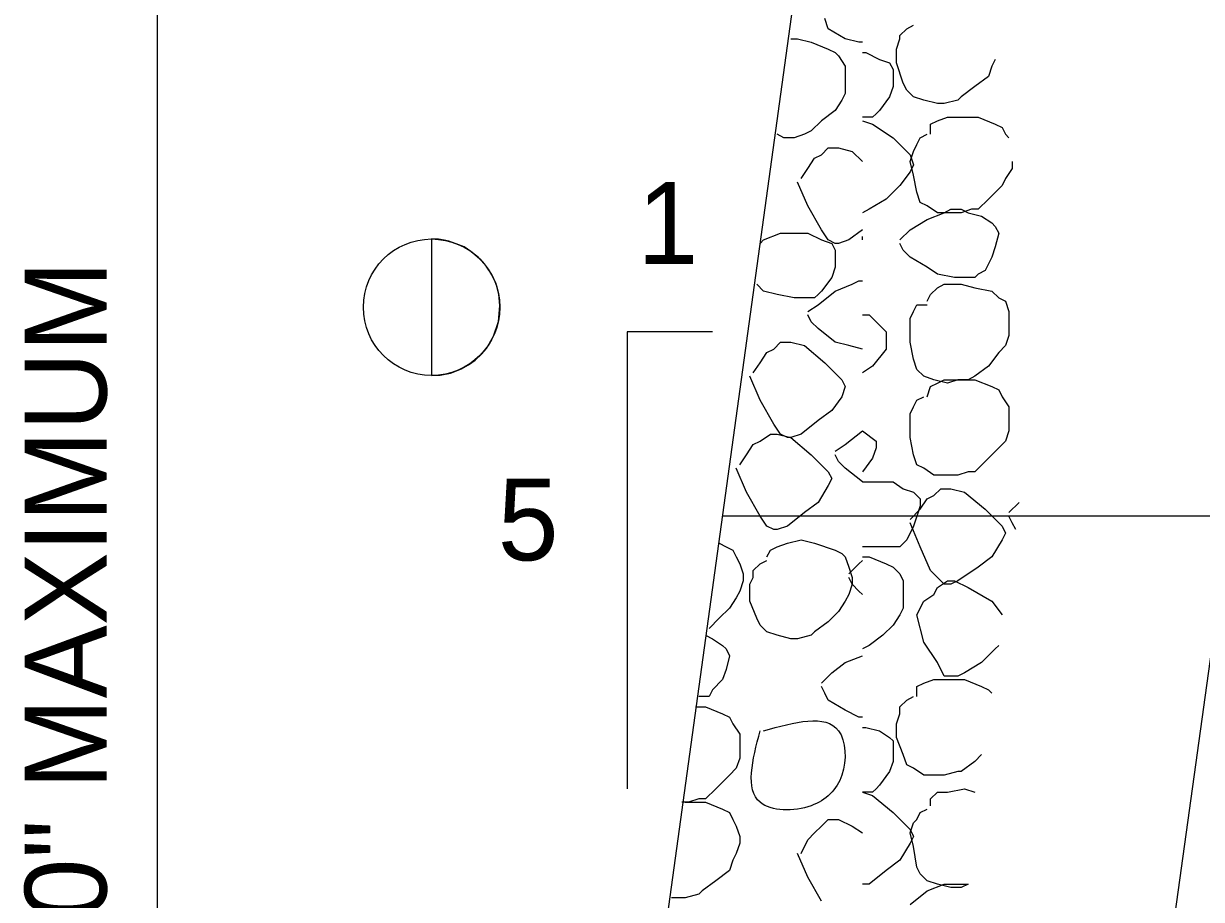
# Model space of a CAD drawing. Extents: x 593 to 1473, y 721 to 1315.
# Drawn here: x 885.01 to 928.22, y 1167.96 to 1200.08 of the extents above; entities that cross this region are included whole.
import ezdxf

# ---------------------------------------------------------------- set-up
doc = ezdxf.new("R2010")
doc.units = 0
doc.layers.add('1', color=7, linetype='Continuous')
doc.layers.add('2', color=7, linetype='Continuous')

msp = doc.modelspace()

# ---------------------------------------------------------------- linework, layer by layer
at = {"layer": '1'}
msp.add_lwpolyline([(899.982, 1192.182), (899.982, 1187.178), (900.301, 1187.189), (900.675, 1187.263), (901.08, 1187.423), (901.335, 1187.562), (901.581, 1187.743), (901.815, 1187.957), (901.996, 1188.17), (902.252, 1188.618), (902.433, 1189.152), (902.487, 1189.739), (902.444, 1190.155), (902.348, 1190.539), (902.188, 1190.88), (901.986, 1191.19), (901.698, 1191.499), (901.421, 1191.723), (901.175, 1191.894), (900.877, 1192.001), (900.611, 1192.108), (900.44, 1192.14), (900.238, 1192.172)], close=True, dxfattribs=at)
msp.add_circle((899.982, 1189.68), 2.502, dxfattribs=at)
at = {"layer": '2'}
for p, q in [((889.933, 1144.896), (889.933, 1219.146)), ((905.533, 1144.896), (915.783, 1219.146)), ((924.158, 1145.021), (934.408, 1219.146)), ((899.982, 1192.182), (899.982, 1187.178)), ((907.158, 1188.771), (907.158, 1172.021)), ((910.283, 1188.771), (907.158, 1188.771)), ((962.283, 1182.021), (910.658, 1182.021))]:
    msp.add_line(p, q, dxfattribs=at)
for points in [[(914.533, 1199.896), (914.408, 1200.271)], [(915.158, 1199.521), (914.533, 1199.896)], [(917.158, 1199.646), (917.408, 1199.896)], [(917.408, 1199.896), (917.658, 1200.021)], [(913.158, 1199.521), (913.408, 1199.521)], [(913.408, 1199.521), (913.908, 1199.396)], [(915.658, 1199.396), (915.158, 1199.521)], [(917.033, 1199.146), (917.158, 1199.521)], [(917.158, 1199.521), (917.158, 1199.646)], [(913.908, 1199.396), (914.533, 1199.146)], [(914.533, 1199.146), (914.783, 1199.021)], [(914.783, 1199.021), (914.908, 1198.896)], [(915.783, 1199.396), (915.658, 1199.396)], [(915.783, 1199.021), (915.908, 1199.021)], [(915.908, 1199.021), (916.408, 1198.771)], [(917.033, 1198.646), (917.033, 1199.146)], [(914.908, 1198.896), (915.158, 1198.521)], [(916.408, 1198.771), (916.783, 1198.646)], [(916.783, 1198.646), (916.908, 1198.396)], [(917.283, 1197.896), (917.033, 1198.646)], [(920.658, 1198.771), (920.533, 1198.521)], [(915.158, 1198.521), (915.158, 1198.146)], [(915.158, 1198.146), (915.158, 1197.896)], [(916.908, 1198.396), (916.908, 1198.271)], [(916.908, 1198.271), (916.908, 1197.771)], [(920.408, 1198.146), (919.908, 1197.771)], [(920.533, 1198.521), (920.408, 1198.146)], [(915.158, 1197.896), (915.158, 1197.521)], [(916.908, 1197.771), (916.783, 1197.396)], [(917.408, 1197.646), (917.283, 1197.896)], [(919.908, 1197.771), (919.408, 1197.396)], [(915.033, 1197.271), (914.783, 1196.896)], [(915.158, 1197.521), (915.033, 1197.271)], [(916.783, 1197.396), (916.408, 1196.896)], [(917.658, 1197.396), (917.408, 1197.646)], [(918.033, 1197.271), (917.658, 1197.396)], [(918.533, 1197.146), (918.033, 1197.271)], [(919.283, 1197.271), (918.783, 1197.146)], [(919.408, 1197.396), (919.283, 1197.271)], [(914.783, 1196.896), (914.283, 1196.521)], [(916.408, 1196.896), (916.283, 1196.771)], [(918.783, 1197.146), (918.533, 1197.146)], [(914.283, 1196.521), (913.908, 1196.146)], [(916.158, 1196.646), (915.783, 1196.646)], [(915.783, 1196.521), (916.158, 1196.396)], [(916.283, 1196.771), (916.158, 1196.646)], [(918.283, 1196.396), (918.533, 1196.521)], [(918.533, 1196.521), (918.908, 1196.646)], [(918.908, 1196.646), (919.533, 1196.646)], [(919.533, 1196.646), (920.033, 1196.646)], [(920.033, 1196.646), (920.658, 1196.396)], [(912.908, 1195.896), (912.658, 1196.021)], [(913.658, 1196.021), (913.283, 1195.896)], [(913.908, 1196.146), (913.658, 1196.021)], [(916.158, 1196.396), (916.908, 1195.896)], [(917.908, 1195.896), (918.158, 1196.021)], [(918.283, 1196.021), (918.283, 1196.396)], [(920.658, 1196.396), (920.908, 1196.271)], [(920.908, 1196.271), (921.033, 1196.021)], [(921.033, 1196.021), (921.158, 1195.896)], [(913.283, 1195.896), (912.908, 1195.896)], [(916.908, 1195.896), (917.533, 1195.271)], [(917.658, 1195.396), (917.783, 1195.646)], [(917.783, 1195.646), (917.908, 1195.896)], [(913.783, 1194.771), (914.033, 1195.146)], [(914.033, 1195.146), (914.283, 1195.271)], [(914.283, 1195.271), (914.533, 1195.521)], [(914.533, 1195.521), (914.783, 1195.521)], [(914.783, 1195.521), (914.908, 1195.521)], [(914.908, 1195.521), (915.408, 1195.396)], [(915.408, 1195.396), (915.783, 1195.021)], [(917.533, 1195.021), (917.658, 1195.396)], [(917.533, 1195.271), (917.658, 1194.896)], [(913.533, 1194.396), (913.783, 1194.771)], [(917.658, 1194.521), (917.533, 1195.021)], [(917.658, 1194.896), (917.533, 1194.646)], [(921.283, 1194.771), (921.033, 1194.396)], [(921.283, 1195.021), (921.283, 1194.771)], [(913.783, 1193.396), (913.408, 1194.271)], [(917.533, 1194.646), (917.158, 1194.146)], [(917.783, 1193.896), (917.658, 1194.521)], [(921.033, 1194.396), (920.908, 1194.146)], [(917.158, 1194.146), (916.658, 1193.646)], [(917.908, 1193.521), (917.783, 1193.896)], [(920.908, 1194.146), (920.408, 1193.646)], [(914.283, 1192.521), (913.783, 1193.396)], [(916.658, 1193.646), (916.033, 1193.271)], [(918.158, 1193.396), (917.908, 1193.521)], [(918.533, 1193.146), (918.158, 1193.396)], [(920.408, 1193.646), (920.033, 1193.271)], [(916.033, 1193.271), (915.783, 1193.146)], [(918.158, 1192.896), (918.783, 1193.146)], [(919.033, 1193.146), (918.533, 1193.146)], [(918.783, 1193.146), (919.033, 1193.271)], [(919.033, 1193.271), (919.408, 1193.271)], [(919.408, 1193.146), (919.033, 1193.146)], [(919.783, 1193.271), (919.408, 1193.146)], [(919.408, 1193.271), (919.658, 1193.146)], [(919.658, 1193.146), (920.158, 1193.021)], [(920.033, 1193.271), (919.783, 1193.271)], [(920.158, 1193.021), (920.533, 1192.771)], [(914.533, 1192.146), (914.283, 1192.521)], [(915.783, 1192.521), (915.283, 1192.146)], [(915.783, 1192.521), (915.783, 1192.521)], [(917.158, 1192.146), (917.533, 1192.521)], [(917.533, 1192.521), (918.158, 1192.896)], [(920.533, 1192.771), (920.658, 1192.646)], [(920.658, 1192.646), (920.783, 1192.396)], [(912.033, 1192.021), (912.158, 1192.146)], [(912.158, 1192.146), (912.783, 1192.396)], [(912.783, 1192.396), (913.033, 1192.396)], [(913.033, 1192.396), (913.408, 1192.396)], [(913.408, 1192.396), (913.783, 1192.396)], [(913.783, 1192.396), (914.283, 1192.146)], [(914.283, 1192.146), (914.658, 1192.021)], [(914.783, 1192.021), (914.533, 1192.146)], [(915.283, 1192.146), (914.908, 1192.021)], [(915.783, 1192.146), (915.783, 1192.271)], [(920.783, 1192.396), (920.658, 1191.896)], [(914.658, 1192.021), (914.783, 1191.771)], [(914.908, 1192.021), (914.783, 1192.021)], [(914.783, 1191.771), (914.783, 1191.646)], [(917.283, 1191.771), (917.158, 1192.021)], [(917.533, 1191.521), (917.283, 1191.771)], [(920.658, 1191.896), (920.533, 1191.521)], [(914.783, 1191.646), (914.783, 1191.146)], [(918.158, 1191.146), (917.533, 1191.521)], [(920.533, 1191.521), (920.283, 1191.021)], [(914.783, 1191.146), (914.658, 1190.771)], [(918.533, 1190.896), (918.158, 1191.146)], [(919.158, 1190.771), (918.533, 1190.896)], [(920.033, 1190.896), (919.908, 1190.771)], [(920.283, 1191.021), (920.033, 1190.896)], [(912.158, 1190.271), (911.908, 1190.521)], [(914.658, 1190.771), (914.283, 1190.271)], [(914.783, 1190.271), (915.408, 1190.521)], [(915.408, 1190.521), (915.658, 1190.646)], [(915.658, 1190.646), (915.783, 1190.646)], [(918.283, 1190.146), (918.533, 1190.396)], [(918.533, 1190.396), (918.783, 1190.521)], [(918.783, 1190.521), (919.408, 1190.521)], [(919.908, 1190.771), (919.158, 1190.771)], [(919.408, 1190.521), (919.908, 1190.396)], [(919.908, 1190.396), (920.533, 1190.271)], [(912.658, 1190.146), (912.158, 1190.271)], [(913.283, 1190.021), (912.658, 1190.146)], [(914.033, 1190.021), (913.283, 1190.021)], [(914.158, 1190.146), (914.033, 1190.021)], [(914.158, 1189.771), (914.783, 1190.271)], [(914.283, 1190.271), (914.158, 1190.146)], [(918.158, 1189.896), (918.283, 1190.146)], [(920.533, 1190.271), (920.783, 1190.021)], [(920.783, 1190.021), (921.033, 1189.896)], [(913.783, 1189.521), (914.158, 1189.771)], [(917.533, 1189.271), (917.658, 1189.521)], [(917.658, 1189.521), (917.783, 1189.771)], [(917.783, 1189.771), (918.158, 1189.771)], [(921.033, 1189.896), (921.158, 1189.521)], [(921.158, 1189.521), (921.158, 1189.146)], [(913.908, 1189.146), (913.783, 1189.396)], [(914.158, 1188.896), (913.908, 1189.146)], [(915.783, 1189.396), (916.033, 1189.396)], [(916.033, 1189.396), (916.658, 1188.771)], [(917.533, 1188.896), (917.533, 1189.271)], [(921.158, 1189.146), (921.158, 1188.896)], [(914.783, 1188.396), (914.158, 1188.896)], [(916.658, 1188.771), (916.658, 1188.396)], [(917.533, 1188.396), (917.533, 1188.896)], [(921.158, 1188.646), (921.033, 1188.271)], [(921.158, 1188.896), (921.158, 1188.646)], [(912.533, 1188.146), (912.783, 1188.396)], [(912.783, 1188.396), (913.033, 1188.396)], [(913.033, 1188.396), (913.158, 1188.396)], [(913.158, 1188.396), (913.658, 1188.271)], [(913.658, 1188.271), (914.408, 1187.646)], [(915.283, 1188.271), (914.783, 1188.396)], [(915.783, 1188.146), (915.283, 1188.271)], [(916.658, 1188.396), (916.658, 1188.146)], [(917.658, 1187.771), (917.533, 1188.396)], [(921.033, 1188.271), (920.783, 1188.021)], [(912.033, 1187.646), (912.283, 1188.021)], [(912.283, 1188.021), (912.533, 1188.146)], [(916.658, 1188.146), (916.158, 1187.521)], [(917.783, 1187.396), (917.658, 1187.771)], [(920.783, 1188.021), (920.408, 1187.521)], [(911.783, 1187.271), (912.033, 1187.646)], [(914.408, 1187.646), (915.033, 1187.021)], [(916.158, 1187.521), (915.783, 1187.271)], [(918.033, 1187.146), (917.783, 1187.396)], [(920.408, 1187.521), (919.908, 1187.146)], [(912.033, 1186.271), (911.658, 1187.146)], [(915.033, 1187.021), (915.158, 1186.771)], [(918.408, 1187.021), (918.033, 1187.146)], [(918.283, 1186.771), (918.533, 1186.896)], [(918.908, 1186.896), (918.408, 1187.021)], [(918.533, 1186.896), (918.783, 1187.021)], [(918.783, 1187.021), (919.408, 1187.021)], [(919.283, 1187.021), (918.908, 1186.896)], [(919.658, 1187.021), (919.283, 1187.021)], [(919.408, 1187.021), (919.908, 1187.021)], [(919.908, 1187.146), (919.658, 1187.021)], [(919.908, 1187.021), (920.533, 1186.771)], [(915.158, 1186.771), (915.033, 1186.396)], [(918.158, 1186.396), (918.283, 1186.771)], [(920.533, 1186.771), (920.783, 1186.646)], [(920.783, 1186.646), (920.908, 1186.396)], [(912.533, 1185.396), (912.033, 1186.271)], [(915.033, 1186.396), (914.658, 1185.896)], [(917.658, 1186.021), (917.783, 1186.271)], [(917.783, 1186.271), (918.033, 1186.396)], [(920.908, 1186.396), (921.158, 1186.021)], [(914.658, 1185.896), (914.158, 1185.521)], [(917.533, 1185.771), (917.658, 1186.021)], [(917.533, 1185.396), (917.533, 1185.771)], [(921.158, 1186.021), (921.158, 1185.771)], [(921.158, 1185.771), (921.158, 1185.521)], [(912.783, 1185.021), (912.533, 1185.396)], [(914.158, 1185.521), (913.533, 1185.021)], [(917.533, 1184.896), (917.533, 1185.396)], [(921.158, 1185.521), (921.158, 1185.146)], [(911.783, 1184.646), (912.033, 1184.771)], [(912.033, 1184.771), (912.408, 1185.021)], [(912.408, 1185.021), (912.533, 1185.021)], [(912.533, 1185.021), (912.658, 1185.021)], [(912.658, 1185.021), (913.158, 1184.896)], [(913.033, 1184.896), (912.783, 1185.021)], [(913.158, 1184.896), (913.033, 1184.896)], [(913.533, 1185.021), (913.158, 1184.896)], [(913.158, 1184.896), (913.908, 1184.271)], [(915.158, 1184.646), (915.783, 1185.146)], [(915.783, 1185.146), (916.283, 1184.771)], [(915.783, 1185.146), (915.783, 1185.146)], [(916.283, 1184.771), (916.283, 1184.521)], [(917.658, 1184.271), (917.533, 1184.896)], [(921.033, 1184.771), (920.783, 1184.521)], [(921.158, 1185.146), (921.033, 1184.771)], [(911.533, 1184.271), (911.783, 1184.646)], [(914.783, 1184.396), (915.158, 1184.646)], [(916.283, 1184.521), (916.158, 1184.146)], [(920.783, 1184.521), (920.283, 1184.021)], [(911.283, 1183.896), (911.533, 1184.271)], [(913.908, 1184.271), (914.533, 1183.646)], [(914.908, 1184.021), (914.783, 1184.271)], [(915.158, 1183.771), (914.908, 1184.021)], [(916.158, 1184.146), (915.783, 1183.646)], [(917.783, 1183.896), (917.658, 1184.271)], [(918.033, 1183.771), (917.783, 1183.896)], [(920.283, 1184.021), (919.908, 1183.646)], [(911.533, 1182.896), (911.158, 1183.771)], [(914.533, 1183.646), (914.658, 1183.396)], [(915.783, 1183.271), (915.158, 1183.771)], [(918.408, 1183.521), (918.033, 1183.771)], [(918.908, 1183.521), (918.408, 1183.521)], [(919.283, 1183.521), (918.908, 1183.521)], [(919.658, 1183.646), (919.283, 1183.521)], [(919.908, 1183.646), (919.658, 1183.646)], [(914.533, 1183.146), (914.158, 1182.521)], [(914.658, 1183.396), (914.533, 1183.146)], [(915.783, 1183.271), (915.908, 1183.271)], [(915.783, 1183.271), (915.783, 1183.271)], [(915.908, 1183.271), (916.158, 1183.271)], [(916.158, 1183.271), (916.533, 1183.271)], [(916.533, 1183.271), (916.908, 1183.271)], [(916.908, 1183.271), (917.283, 1183.021)], [(917.283, 1183.021), (917.658, 1182.896)], [(918.408, 1182.771), (918.658, 1183.021)], [(918.658, 1183.021), (918.783, 1183.021)], [(918.783, 1183.021), (919.033, 1183.021)], [(919.033, 1183.021), (919.533, 1182.896)], [(912.033, 1182.021), (911.533, 1182.896)], [(917.658, 1182.896), (917.908, 1182.646)], [(917.908, 1182.646), (917.908, 1182.396)], [(917.908, 1182.271), (918.158, 1182.646)], [(918.158, 1182.646), (918.408, 1182.771)], [(919.533, 1182.896), (920.283, 1182.271)], [(913.658, 1182.146), (913.033, 1181.646)], [(914.158, 1182.521), (913.658, 1182.146)], [(917.533, 1181.896), (917.908, 1182.271)], [(917.908, 1182.396), (917.783, 1182.021)], [(920.283, 1182.271), (920.908, 1181.646)], [(921.158, 1182.146), (921.533, 1182.521)], [(921.533, 1182.521), (921.533, 1182.521)], [(912.283, 1181.646), (912.033, 1182.021)], [(917.908, 1180.896), (917.533, 1181.771)], [(917.783, 1182.021), (917.658, 1181.646)], [(921.283, 1181.771), (921.158, 1182.021)], [(921.408, 1181.521), (921.283, 1181.771)], [(912.533, 1181.521), (912.283, 1181.646)], [(912.658, 1181.521), (912.533, 1181.521)], [(913.033, 1181.646), (912.658, 1181.521)], [(917.658, 1181.646), (917.408, 1181.146)], [(920.908, 1181.646), (921.033, 1181.396)], [(921.033, 1181.396), (920.908, 1181.146)], [(910.533, 1181.021), (910.783, 1180.896)], [(910.783, 1180.896), (911.033, 1180.771)], [(912.408, 1180.771), (912.658, 1180.896)], [(912.658, 1180.896), (913.033, 1181.021)], [(913.033, 1181.021), (913.533, 1181.146)], [(913.533, 1181.146), (914.033, 1181.021)], [(914.033, 1181.021), (914.783, 1180.771)], [(916.408, 1180.896), (915.783, 1180.896)], [(917.033, 1180.896), (916.408, 1180.896)], [(917.158, 1180.896), (917.033, 1180.896)], [(917.408, 1181.146), (917.158, 1180.896)], [(918.283, 1180.021), (917.908, 1180.896)], [(920.908, 1181.146), (920.533, 1180.521)], [(911.033, 1180.771), (911.158, 1180.521)], [(911.158, 1180.521), (911.283, 1180.271)], [(912.283, 1180.521), (912.408, 1180.771)], [(914.783, 1180.771), (915.033, 1180.646)], [(915.033, 1180.646), (915.158, 1180.521)], [(915.158, 1180.521), (915.283, 1180.146)], [(915.783, 1180.521), (916.033, 1180.521)], [(916.033, 1180.521), (916.658, 1180.271)], [(920.533, 1180.521), (920.033, 1180.146)], [(911.283, 1180.271), (911.408, 1179.896)], [(911.783, 1180.021), (912.033, 1180.271)], [(911.783, 1179.771), (911.783, 1180.021)], [(912.033, 1180.271), (912.283, 1180.396)], [(915.283, 1179.896), (915.658, 1180.271)], [(915.283, 1180.146), (915.408, 1179.771)], [(915.658, 1180.271), (915.783, 1180.396)], [(916.658, 1180.271), (916.908, 1180.146)], [(916.908, 1180.146), (917.158, 1179.896)], [(918.658, 1179.646), (918.283, 1180.021)], [(920.033, 1180.146), (919.283, 1179.646)], [(911.408, 1179.646), (911.283, 1179.271)], [(911.408, 1179.896), (911.408, 1179.646)], [(911.658, 1179.521), (911.783, 1179.771)], [(915.408, 1179.521), (915.283, 1179.771)], [(915.408, 1179.771), (915.408, 1179.521)], [(917.158, 1179.896), (917.283, 1179.646)], [(917.283, 1179.646), (917.283, 1179.271)], [(918.533, 1179.396), (918.908, 1179.646)], [(918.783, 1179.521), (918.658, 1179.646)], [(918.908, 1179.646), (919.033, 1179.646)], [(919.033, 1179.646), (919.158, 1179.646)], [(919.283, 1179.646), (919.033, 1179.521)], [(919.158, 1179.646), (919.658, 1179.396)], [(911.283, 1179.271), (911.158, 1179.021)], [(911.658, 1178.896), (911.658, 1179.521)], [(915.283, 1179.146), (915.158, 1178.896)], [(915.408, 1179.521), (915.283, 1179.146)], [(915.658, 1179.271), (915.408, 1179.521)], [(915.783, 1179.146), (915.658, 1179.271)], [(917.283, 1179.271), (917.283, 1179.021)], [(918.033, 1178.896), (918.408, 1179.146)], [(918.408, 1179.146), (918.533, 1179.396)], [(919.033, 1179.521), (918.783, 1179.521)], [(919.658, 1179.396), (920.533, 1178.896)], [(911.158, 1179.021), (910.908, 1178.646)], [(911.908, 1178.271), (911.658, 1178.896)], [(915.158, 1178.896), (914.908, 1178.521)], [(917.283, 1179.021), (917.283, 1178.646)], [(917.783, 1178.396), (918.033, 1178.896)], [(920.533, 1178.896), (920.908, 1178.396)], [(910.533, 1178.271), (910.158, 1177.896)], [(910.908, 1178.646), (910.533, 1178.271)], [(912.033, 1178.021), (911.908, 1178.271)], [(914.908, 1178.521), (914.533, 1178.146)], [(917.158, 1178.396), (916.908, 1178.021)], [(917.283, 1178.646), (917.158, 1178.396)], [(918.033, 1177.396), (917.783, 1178.396)], [(912.283, 1177.771), (912.033, 1178.021)], [(914.533, 1178.146), (914.033, 1177.771)], [(916.908, 1178.021), (916.533, 1177.646)], [(910.033, 1177.646), (910.283, 1177.521)], [(910.283, 1177.521), (910.658, 1177.271)], [(912.658, 1177.646), (912.283, 1177.771)], [(913.158, 1177.521), (912.658, 1177.646)], [(913.408, 1177.521), (913.158, 1177.521)], [(913.908, 1177.646), (913.408, 1177.521)], [(914.033, 1177.771), (913.908, 1177.646)], [(916.533, 1177.646), (916.033, 1177.271)], [(918.533, 1176.646), (918.033, 1177.396)], [(910.658, 1177.271), (910.783, 1177.146)], [(910.783, 1177.146), (910.908, 1176.896)], [(916.033, 1177.271), (915.783, 1177.146)], [(920.658, 1177.146), (920.158, 1176.646)], [(920.783, 1177.271), (920.658, 1177.146)], [(910.908, 1176.896), (910.783, 1176.396)], [(914.658, 1176.271), (915.158, 1176.646)], [(915.158, 1176.646), (915.783, 1176.896)], [(918.783, 1176.146), (918.533, 1176.646)], [(920.158, 1176.646), (919.533, 1176.271)], [(910.783, 1176.396), (910.658, 1176.021)], [(914.283, 1175.896), (914.658, 1176.271)], [(919.033, 1176.146), (918.783, 1176.146)], [(919.283, 1176.146), (919.033, 1176.146)], [(919.533, 1176.271), (919.283, 1176.146)], [(910.658, 1176.021), (910.283, 1175.646)], [(914.408, 1175.521), (914.283, 1175.771)], [(917.783, 1175.771), (918.033, 1175.896)], [(917.783, 1175.396), (917.783, 1175.771)], [(918.033, 1175.896), (918.408, 1176.021)], [(918.408, 1176.021), (919.033, 1176.021)], [(919.033, 1176.021), (919.533, 1176.021)], [(919.533, 1176.021), (920.158, 1175.771)], [(920.158, 1175.771), (920.408, 1175.646)], [(910.033, 1175.396), (909.783, 1175.396)], [(910.158, 1175.396), (910.033, 1175.396)], [(910.283, 1175.646), (910.158, 1175.396)], [(914.533, 1175.271), (914.408, 1175.521)], [(915.158, 1174.896), (914.533, 1175.271)], [(917.158, 1175.021), (917.408, 1175.271)], [(917.408, 1175.271), (917.658, 1175.396)], [(920.408, 1175.646), (920.533, 1175.521)], [(909.658, 1175.021), (910.033, 1175.021)], [(910.033, 1175.021), (910.658, 1174.771)], [(915.658, 1174.646), (915.158, 1174.896)], [(917.158, 1174.771), (917.158, 1175.021)], [(910.658, 1174.771), (910.908, 1174.646)], [(910.908, 1174.646), (911.033, 1174.396)], [(911.033, 1174.396), (911.283, 1174.021)], [(915.783, 1174.646), (915.658, 1174.646)], [(917.033, 1174.396), (917.158, 1174.771)], [(917.033, 1173.896), (917.033, 1174.396)], [(911.283, 1174.021), (911.283, 1173.771)], [(915.783, 1174.271), (915.908, 1174.271)], [(915.908, 1174.271), (916.408, 1174.146)], [(916.408, 1174.146), (916.783, 1173.896)], [(911.283, 1173.771), (911.283, 1173.521)], [(911.283, 1173.521), (911.283, 1173.146)], [(916.783, 1173.896), (916.908, 1173.771)], [(916.908, 1173.771), (916.908, 1173.521)], [(916.908, 1173.521), (916.908, 1173.021)], [(917.283, 1173.271), (917.033, 1173.896)], [(911.283, 1173.146), (911.158, 1172.771)], [(917.408, 1172.896), (917.283, 1173.271)], [(920.158, 1173.271), (919.908, 1173.021)], [(911.158, 1172.771), (910.908, 1172.521)], [(916.783, 1172.646), (916.408, 1172.146)], [(916.908, 1173.021), (916.783, 1172.646)], [(917.658, 1172.771), (917.408, 1172.896)], [(918.033, 1172.521), (917.658, 1172.771)], [(919.283, 1172.646), (918.783, 1172.521)], [(919.408, 1172.646), (919.283, 1172.646)], [(919.908, 1173.021), (919.408, 1172.646)], [(910.908, 1172.521), (910.408, 1172.021)], [(918.533, 1172.521), (918.033, 1172.521)], [(918.783, 1172.521), (918.533, 1172.521)], [(910.408, 1172.021), (910.033, 1171.646)], [(915.783, 1171.896), (916.158, 1171.771)], [(916.158, 1171.896), (915.783, 1171.896)], [(916.283, 1172.021), (916.158, 1171.896)], [(916.408, 1172.146), (916.283, 1172.021)], [(918.283, 1171.646), (918.533, 1171.896)], [(918.533, 1171.896), (918.908, 1171.896)], [(918.908, 1171.896), (919.533, 1172.021)], [(919.533, 1172.021), (919.908, 1171.896)], [(909.408, 1171.521), (909.158, 1171.521)], [(909.283, 1171.521), (909.533, 1171.521)], [(909.783, 1171.646), (909.408, 1171.521)], [(909.533, 1171.521), (910.033, 1171.521)], [(910.033, 1171.646), (909.783, 1171.646)], [(910.033, 1171.521), (910.658, 1171.271)], [(916.158, 1171.771), (916.908, 1171.146)], [(918.283, 1171.396), (918.283, 1171.646)], [(910.658, 1171.271), (910.908, 1171.146)], [(910.908, 1171.146), (911.033, 1170.896)], [(916.908, 1171.146), (917.533, 1170.521)], [(917.783, 1170.896), (917.908, 1171.146)], [(917.908, 1171.146), (918.158, 1171.271)], [(911.033, 1170.896), (911.158, 1170.646)], [(911.158, 1170.646), (911.283, 1170.271)], [(914.033, 1170.396), (914.283, 1170.646)], [(914.283, 1170.646), (914.533, 1170.896)], [(914.533, 1170.896), (914.783, 1170.896)], [(914.783, 1170.896), (914.908, 1170.896)], [(914.908, 1170.896), (915.408, 1170.646)], [(915.408, 1170.646), (915.783, 1170.396)], [(917.533, 1170.396), (917.658, 1170.771)], [(917.533, 1170.521), (917.658, 1170.271)], [(917.658, 1170.771), (917.783, 1170.896)], [(911.283, 1170.271), (911.283, 1170.021)], [(913.533, 1169.646), (913.783, 1170.146)], [(913.783, 1170.146), (914.033, 1170.396)], [(917.658, 1169.896), (917.533, 1170.396)], [(917.658, 1170.271), (917.533, 1170.021)], [(911.158, 1169.646), (911.033, 1169.396)], [(911.283, 1170.021), (911.158, 1169.646)], [(913.783, 1168.771), (913.408, 1169.646)], [(917.533, 1170.021), (917.158, 1169.396)], [(917.783, 1169.146), (917.658, 1169.896)], [(911.033, 1169.396), (910.908, 1169.021)], [(917.158, 1169.396), (916.658, 1169.021)], [(910.908, 1169.021), (910.408, 1168.646)], [(914.283, 1167.896), (913.783, 1168.771)], [(916.658, 1169.021), (916.033, 1168.521)], [(917.908, 1168.896), (917.783, 1169.146)], [(918.158, 1168.646), (917.908, 1168.896)], [(910.408, 1168.646), (909.908, 1168.271)], [(916.033, 1168.521), (915.783, 1168.521)], [(918.533, 1168.521), (918.158, 1168.646)], [(918.158, 1168.271), (918.783, 1168.521)], [(919.033, 1168.396), (918.533, 1168.521)], [(918.783, 1168.521), (919.033, 1168.521)], [(919.033, 1168.521), (919.408, 1168.521)], [(919.408, 1168.396), (919.033, 1168.396)], [(919.658, 1168.521), (919.408, 1168.396)], [(919.408, 1168.521), (919.658, 1168.521)], [(909.033, 1168.021), (908.783, 1168.021)], [(909.283, 1168.021), (909.033, 1168.021)], [(909.783, 1168.146), (909.283, 1168.021)], [(909.908, 1168.271), (909.783, 1168.146)], [(917.533, 1167.771), (918.158, 1168.271)]]:
    msp.add_lwpolyline(points, dxfattribs=at)
msp.add_spline([(912.158, 1174.146), (914.908, 1174.146), (915.033, 1172.521), (913.908, 1171.396), (912.033, 1171.521), (912.033, 1174.146)], degree=3, dxfattribs=at)

# ---------------------------------------------------------------- texts
for s, p in [('1', (907.533, 1191.271)), ('5', (902.408, 1180.396))]:
    msp.add_text(s, height=3, dxfattribs=at).set_placement(p)
msp.add_text('12\'-0" MAXIMUM ', height=3, rotation=90, dxfattribs=at).set_placement((888.058, 1160.663))

doc.saveas('drawing.dxf')
